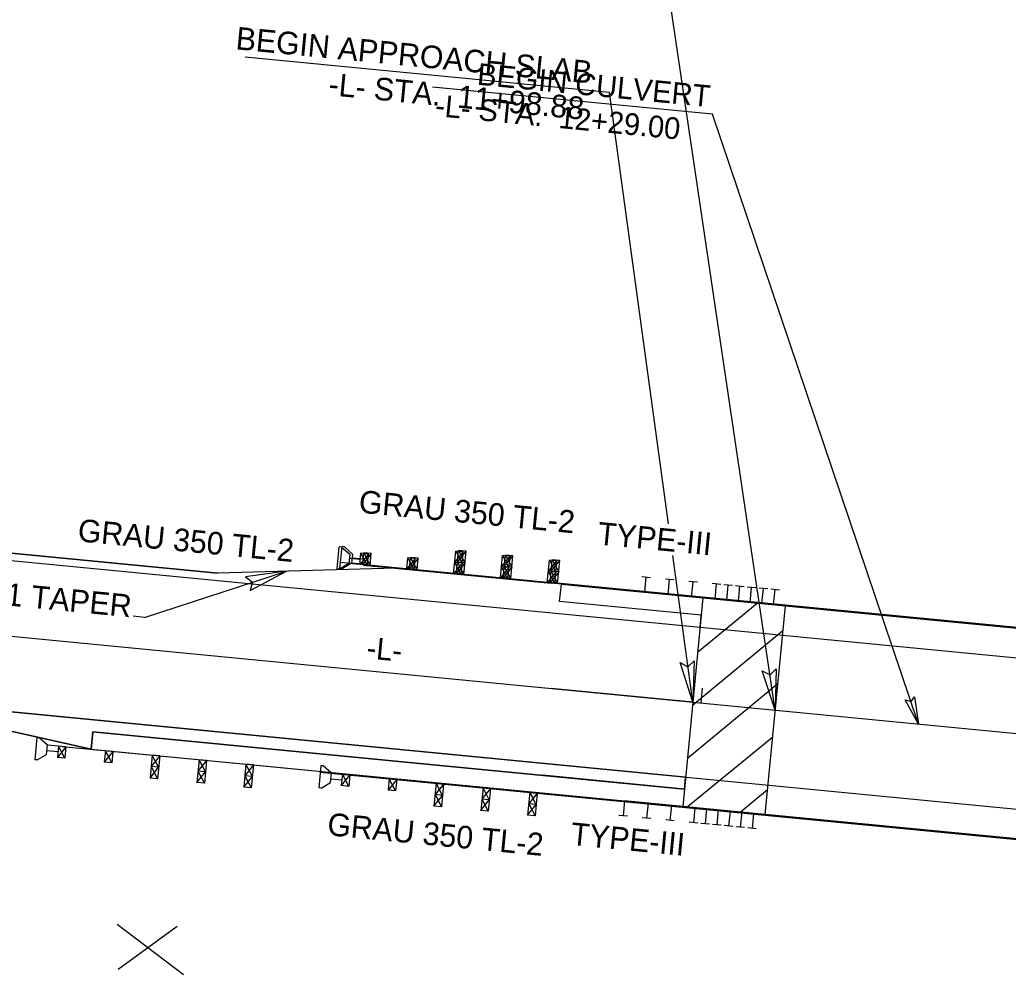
# Model space of a CAD drawing. Extents: x 2061030 to 2061632, y 912568 to 912882.
# Drawn here: x 2061138.9 to 2061270.2, y 912666.3 to 912794.9 of the extents above; entities that cross this region are included whole.
import ezdxf

# ---------------------------------------------------------------- set-up
doc = ezdxf.new("R2010")
doc.units = 0
for name, color, linetype in [('Prop Approach Slab', 7, 'Continuous'), ('Prop Approach Slab Hatching', 7, 'Continuous'), ('Prop Conc Shoulder Berm Gutter', 7, 'Continuous'), ('Prop Dimension', 7, 'Continuous'), ('Prop Dimension Text', 7, 'Continuous'), ('Prop EOT', 7, 'Continuous'), ('Prop Guardrail', 7, 'Continuous'), ('Prop Guardrail Anchor Unit CELL', 7, 'Continuous'), ('Prop Horizontal Alignment', 7, 'Continuous'), ('Prop Horizontal Alignment Station Label', 7, 'Continuous'), ('Prop Horizontal Alignment Tick Small', 7, 'Continuous'), ('Prop Paved Shoulder', 7, 'Continuous'), ('Prop Roadway Bridge', 7, 'Continuous'), ('Prop Shade Medium', 7, 'Continuous'), ('Prop Structure Anchor Unit CELL', 7, 'Continuous'), ('Prop Terminator CELL', 7, 'Continuous'), ('Scratch_Level_0', 7, 'Continuous')]:
    doc.layers.add(name, color=color, linetype=linetype)

msp = doc.modelspace()

# ---------------------------------------------------------------- linework, layer by layer
at = {"layer": 'Prop Approach Slab'}
for p, q in [((2061229.63, 912718.13), (2061226.95, 912690.43)), ((2061229.63, 912718.13), (2061240.58, 912717.07)), ((2061226.95, 912690.43), (2061237.9, 912689.37))]:
    msp.add_line(p, q, dxfattribs=at)
at = {"layer": 'Prop Approach Slab Hatching'}
for p, q in [((2061228.93, 912710.93), (2061236.83, 912717.44)), ((2061228.25, 912703.89), (2061240.26, 912713.78)), ((2061227.57, 912696.85), (2061239.58, 912706.74)), ((2061227.56, 912690.37), (2061238.9, 912699.7)), ((2061234.6, 912689.69), (2061238.22, 912692.67))]:
    msp.add_line(p, q, dxfattribs=at)
at = {"layer": 'Prop Conc Shoulder Berm Gutter'}
for p, q in [((2061210.84, 912719.95), (2061229.63, 912718.13)), ((2061228.29, 912704.28), (2061209.5, 912706.1)), ((2061148.66, 912700.34), (2061227.17, 912692.75)), ((2061148.44, 912698.02), (2061226.95, 912690.43))]:
    msp.add_line(p, q, dxfattribs=at)
at = {"layer": 'Prop Dimension'}
for q in [(2061174.36, 912721.68), (2061154.01, 912715.68)]:
    msp.add_line((2061155.5, 912715.53), q, dxfattribs=at)
at = {"layer": 'Prop Dimension Text'}
for p, q in [((2061151.88, 912674.8), (2061160.68, 912668.11)), ((2061159.84, 912674.49), (2061151.99, 912668.8))]:
    msp.add_line(p, q, dxfattribs=at)
at = {"layer": 'Prop EOT'}
for p, q in [((2061105.95, 912726.15), (2061429.44, 912694.88)), ((2061104.02, 912706.25), (2061477.28, 912670.17))]:
    msp.add_line(p, q, dxfattribs=at)
at = {"layer": 'Prop Guardrail'}
for p, q in [((2061221.91, 912718.88), (2061209.47, 912720.08)), ((2061169.47, 912695.99), (2061219.24, 912691.17))]:
    msp.add_line(p, q, dxfattribs=at)
at = {"layer": 'Prop Guardrail Anchor Unit CELL'}
for p, q in [((2061181.07, 912721.98), (2061181.35, 912724.9)), ((2061181.66, 912724.87), (2061181.35, 912724.9)), ((2061181.66, 912724.87), (2061182.75, 912723.91)), ((2061182.75, 912723.91), (2061182.63, 912722.69)), ((2061182.7, 912723.41), (2061184.16, 912723.26)), ((2061184.09, 912722.54), (2061184.24, 912724.05)), ((2061185.23, 912723.95), (2061184.09, 912722.54)), ((2061185.23, 912723.95), (2061184.24, 912724.05)), ((2061185.09, 912722.44), (2061184.24, 912724.05)), ((2061185.09, 912722.44), (2061185.23, 912723.95)), ((2061190.31, 912721.93), (2061190.46, 912723.45)), ((2061191.45, 912723.35), (2061190.31, 912721.93)), ((2061191.45, 912723.35), (2061190.46, 912723.45)), ((2061191.31, 912721.84), (2061190.46, 912723.45)), ((2061191.31, 912721.84), (2061191.45, 912723.35)), ((2061196.53, 912721.33), (2061196.82, 912724.35)), ((2061196.68, 912722.84), (2061197.82, 912724.26)), ((2061197.82, 912724.26), (2061196.82, 912724.35)), ((2061196.82, 912724.35), (2061197.67, 912722.75)), ((2061197.53, 912721.24), (2061197.82, 912724.26)), ((2061202.75, 912720.73), (2061203.05, 912723.75)), ((2061202.9, 912722.24), (2061204.04, 912723.66)), ((2061204.04, 912723.66), (2061203.05, 912723.75)), ((2061203.05, 912723.75), (2061203.89, 912722.15)), ((2061203.75, 912720.63), (2061204.04, 912723.66)), ((2061181.37, 912721.95), (2061181.07, 912721.98)), ((2061182.63, 912722.69), (2061181.37, 912721.95)), ((2061184.09, 912722.55), (2061182.63, 912722.69)), ((2061185.09, 912722.44), (2061184.09, 912722.54)), ((2061184.59, 912722.49), (2061209.47, 912720.08)), ((2061197.67, 912722.75), (2061196.53, 912721.33)), ((2061197.67, 912722.75), (2061196.68, 912722.84)), ((2061197.53, 912721.24), (2061196.68, 912722.84)), ((2061203.89, 912722.15), (2061202.75, 912720.73)), ((2061203.89, 912722.15), (2061202.9, 912722.24)), ((2061203.75, 912720.63), (2061202.9, 912722.24)), ((2061208.97, 912720.13), (2061209.27, 912723.15)), ((2061209.12, 912721.64), (2061210.26, 912723.06)), ((2061210.26, 912723.06), (2061209.27, 912723.15)), ((2061209.27, 912723.15), (2061210.12, 912721.54)), ((2061209.97, 912720.03), (2061210.26, 912723.06)), ((2061191.31, 912721.84), (2061190.31, 912721.93)), ((2061197.53, 912721.24), (2061196.53, 912721.33)), ((2061203.75, 912720.63), (2061202.75, 912720.73)), ((2061210.12, 912721.54), (2061208.97, 912720.13)), ((2061210.12, 912721.54), (2061209.12, 912721.64)), ((2061209.97, 912720.03), (2061209.12, 912721.64)), ((2061209.97, 912720.03), (2061208.97, 912720.13)), ((2061141.23, 912699.57), (2061140.95, 912696.64)), ((2061141.53, 912699.54), (2061141.23, 912699.57)), ((2061142.62, 912698.57), (2061141.53, 912699.54)), ((2061142.5, 912697.35), (2061142.62, 912698.57)), ((2061144.09, 912698.43), (2061142.62, 912698.57)), ((2061144.09, 912698.44), (2061143.94, 912696.93)), ((2061145.08, 912698.34), (2061143.94, 912696.93)), ((2061145.08, 912698.34), (2061144.09, 912698.44)), ((2061144.94, 912696.83), (2061144.09, 912698.44)), ((2061144.58, 912698.39), (2061169.47, 912695.99)), ((2061145.08, 912698.34), (2061144.94, 912696.83)), ((2061141.25, 912696.61), (2061142.5, 912697.35)), ((2061142.55, 912697.85), (2061144.02, 912697.71)), ((2061150.31, 912697.84), (2061150.16, 912696.33)), ((2061151.3, 912697.74), (2061150.16, 912696.33)), ((2061151.3, 912697.74), (2061150.31, 912697.84)), ((2061151.16, 912696.23), (2061150.31, 912697.84)), ((2061151.3, 912697.74), (2061151.16, 912696.23)), ((2061156.53, 912697.24), (2061156.24, 912694.21)), ((2061157.52, 912697.14), (2061156.38, 912695.73)), ((2061157.52, 912697.14), (2061156.53, 912697.24)), ((2061157.38, 912695.63), (2061156.53, 912697.24)), ((2061157.52, 912697.14), (2061157.23, 912694.12)), ((2061141.25, 912696.61), (2061140.95, 912696.64)), ((2061144.94, 912696.83), (2061143.94, 912696.93)), ((2061151.16, 912696.23), (2061150.16, 912696.33)), ((2061157.38, 912695.63), (2061156.38, 912695.73)), ((2061156.38, 912695.73), (2061157.23, 912694.12)), ((2061162.75, 912696.64), (2061162.46, 912693.61)), ((2061163.74, 912696.54), (2061162.6, 912695.12)), ((2061163.74, 912696.54), (2061162.75, 912696.64)), ((2061163.6, 912695.03), (2061162.75, 912696.64)), ((2061163.74, 912696.54), (2061163.45, 912693.52)), ((2061168.97, 912696.03), (2061168.68, 912693.01)), ((2061169.97, 912695.94), (2061168.82, 912694.52)), ((2061169.97, 912695.94), (2061168.97, 912696.03)), ((2061169.82, 912694.43), (2061168.97, 912696.03)), ((2061169.97, 912695.94), (2061169.67, 912692.92)), ((2061156.24, 912694.21), (2061157.38, 912695.63)), ((2061162.46, 912693.61), (2061163.6, 912695.03)), ((2061163.6, 912695.03), (2061162.6, 912695.12)), ((2061162.6, 912695.12), (2061163.45, 912693.52)), ((2061168.68, 912693.01), (2061169.82, 912694.43)), ((2061169.82, 912694.43), (2061168.82, 912694.52)), ((2061168.82, 912694.52), (2061169.67, 912692.92)), ((2061157.23, 912694.12), (2061156.24, 912694.21)), ((2061163.45, 912693.52), (2061162.46, 912693.61)), ((2061169.67, 912692.92), (2061168.68, 912693.01))]:
    msp.add_line(p, q, dxfattribs=at)
at = {"layer": 'Prop Horizontal Alignment'}
msp.add_line((2061030.33, 912723.42), (2061621.2, 912666.3), dxfattribs=at)
at = {"layer": 'Prop Horizontal Alignment Station Label'}
for p, q in [((2061239.24, 912703.22), (2061224.98, 912799.33)), ((2061217.22, 912785.22), (2061168.86, 912789.9)), ((2061225.05, 912727.96), (2061217.22, 912785.22)), ((2061228.29, 912704.28), (2061225.62, 912723.76))]:
    msp.add_line(p, q, dxfattribs=at)
at = {"layer": 'Prop Horizontal Alignment Tick Small'}
msp.add_line((2061229.4, 912704.17), (2061229.6, 912706.16), dxfattribs=at)
at = {"layer": 'Prop Paved Shoulder'}
for p, q in [((2061106.04, 912727.15), (2061165.24, 912721.43)), ((2061210.84, 912719.95), (2061210.84, 912719.95)), ((2061229.63, 912718.13), (2061240.58, 912717.07)), ((2061148.44, 912698.02), (2061125.49, 912703.17)), ((2061148.66, 912700.34), (2061148.44, 912698.02)), ((2061227.17, 912692.75), (2061148.66, 912700.34)), ((2061226.95, 912690.43), (2061237.9, 912689.37))]:
    msp.add_line(p, q, dxfattribs=at)
msp.add_lwpolyline([(2061229.4, 912715.81), (2061210.61, 912717.63), (2061210.84, 912719.95), (2061201.36, 912720.87), (2061188.85, 912722.09), (2061165.24, 912721.43)], dxfattribs=at)
at = {"layer": 'Prop Roadway Bridge'}
for p, q in [((2061237.9, 912689.37), (2061240.58, 912717.07)), ((2061240.58, 912717.07), (2061312.49, 912710.12)), ((2061309.81, 912682.42), (2061237.9, 912689.37))]:
    msp.add_line(p, q, dxfattribs=at)
at = {"layer": 'Prop Shade Medium'}
for p, q in [((2061105.95, 912726.15), (2061229.25, 912714.23)), ((2061165.24, 912721.43), (2061106.04, 912727.15)), ((2061229.25, 912714.23), (2061229.4, 912715.81)), ((2061227.33, 912694.33), (2061104.02, 912706.25)), ((2061227.17, 912692.75), (2061227.33, 912694.33))]:
    msp.add_line(p, q, dxfattribs=at)
for points in [[(2061229.4, 912715.81), (2061210.61, 912717.63), (2061210.84, 912719.95), (2061201.36, 912720.87), (2061188.85, 912722.09), (2061165.24, 912721.43)], [(2061125.49, 912703.17), (2061148.44, 912698.02), (2061148.66, 912700.34), (2061227.17, 912692.75), (2061208.38, 912694.57), (2061227.17, 912692.75)]]:
    msp.add_lwpolyline(points, dxfattribs=at)
at = {"layer": 'Prop Structure Anchor Unit CELL'}
for p, q in [((2061222.68, 912720.81), (2061221.54, 912720.92)), ((2061221.91, 912718.88), (2061222.11, 912720.87)), ((2061225.79, 912720.51), (2061224.65, 912720.62)), ((2061225.02, 912718.58), (2061225.22, 912720.57)), ((2061228.9, 912720.21), (2061227.76, 912720.32)), ((2061228.13, 912718.28), (2061228.33, 912720.27)), ((2061232.01, 912719.91), (2061230.87, 912720.02)), ((2061231.25, 912717.98), (2061231.44, 912719.97)), ((2061233.56, 912719.76), (2061232.42, 912719.87)), ((2061232.8, 912717.83), (2061232.99, 912719.82)), ((2061235.12, 912719.61), (2061233.98, 912719.72)), ((2061234.36, 912717.68), (2061234.55, 912719.67)), ((2061236.67, 912719.46), (2061235.53, 912719.57)), ((2061235.91, 912717.53), (2061236.1, 912719.52)), ((2061238.23, 912719.31), (2061237.09, 912719.42)), ((2061237.47, 912717.38), (2061237.66, 912719.37)), ((2061240.58, 912717.07), (2061221.91, 912718.88)), ((2061239.78, 912719.16), (2061238.64, 912719.27)), ((2061239.02, 912717.23), (2061239.21, 912719.22)), ((2061219.24, 912691.17), (2061219.04, 912689.18)), ((2061237.9, 912689.37), (2061219.24, 912691.17)), ((2061222.35, 912690.87), (2061222.15, 912688.88)), ((2061225.46, 912690.57), (2061225.26, 912688.58)), ((2061219.61, 912689.13), (2061218.47, 912689.24)), ((2061228.57, 912690.27), (2061228.37, 912688.28)), ((2061230.12, 912690.12), (2061229.93, 912688.13)), ((2061231.68, 912689.97), (2061231.49, 912687.98)), ((2061233.23, 912689.82), (2061233.04, 912687.83)), ((2061234.79, 912689.67), (2061234.6, 912687.68)), ((2061236.34, 912689.52), (2061236.15, 912687.53)), ((2061222.72, 912688.83), (2061221.58, 912688.94)), ((2061225.83, 912688.53), (2061224.69, 912688.64)), ((2061228.94, 912688.23), (2061227.8, 912688.34)), ((2061230.5, 912688.08), (2061229.36, 912688.19)), ((2061232.06, 912687.93), (2061230.92, 912688.04)), ((2061233.61, 912687.78), (2061232.47, 912687.89)), ((2061235.17, 912687.63), (2061234.03, 912687.74)), ((2061236.72, 912687.48), (2061235.58, 912687.59))]:
    msp.add_line(p, q, dxfattribs=at)
at = {"layer": 'Prop Terminator CELL'}
for points in [[(2061169.51, 912719.12), (2061174.36, 912721.68), (2061168.9, 912720.91), (2061169.85, 912720.21)], [(2061228.48, 912709.76), (2061228.29, 912704.28), (2061226.6, 912709.53), (2061227.65, 912708.98)], [(2061239.37, 912708.7), (2061239.24, 912703.22), (2061237.49, 912708.45), (2061238.54, 912707.91)]]:
    msp.add_lwpolyline(points, close=True, dxfattribs=at)
at = {"layer": 'Scratch_Level_0'}
for p, q in [((2061230.91, 912782.34), (2061193.74, 912785.93)), ((2061258.27, 912701.38), (2061230.91, 912782.34)), ((2061181.44, 912722.03), (2061181.73, 912724.95)), ((2061182.04, 912724.92), (2061181.73, 912724.95)), ((2061182.04, 912724.92), (2061183.12, 912723.95)), ((2061183.12, 912723.95), (2061183, 912722.74)), ((2061183.07, 912723.45), (2061184.54, 912723.31)), ((2061184.47, 912722.58), (2061184.61, 912724.09)), ((2061185.61, 912724), (2061184.47, 912722.58)), ((2061185.61, 912724), (2061184.61, 912724.09)), ((2061185.46, 912722.49), (2061184.61, 912724.09)), ((2061185.46, 912722.49), (2061185.61, 912724)), ((2061190.69, 912721.98), (2061190.83, 912723.49)), ((2061191.83, 912723.4), (2061190.69, 912721.98)), ((2061191.83, 912723.4), (2061190.83, 912723.49)), ((2061191.68, 912721.88), (2061190.83, 912723.49)), ((2061191.68, 912721.88), (2061191.83, 912723.4)), ((2061196.91, 912721.38), (2061197.2, 912724.4)), ((2061197.05, 912722.89), (2061198.2, 912724.31)), ((2061198.2, 912724.31), (2061197.2, 912724.4)), ((2061197.2, 912724.4), (2061198.05, 912722.79)), ((2061197.9, 912721.28), (2061198.2, 912724.31)), ((2061203.13, 912720.78), (2061203.42, 912723.8)), ((2061203.27, 912722.29), (2061204.42, 912723.7)), ((2061204.42, 912723.7), (2061203.42, 912723.8)), ((2061203.42, 912723.8), (2061204.27, 912722.19)), ((2061204.12, 912720.68), (2061204.42, 912723.7)), ((2061181.75, 912722), (2061181.44, 912722.03)), ((2061181.53, 912722.87), (2061373.54, 912704.31)), ((2061183, 912722.74), (2061181.75, 912722)), ((2061184.47, 912722.59), (2061183, 912722.74)), ((2061185.46, 912722.49), (2061184.47, 912722.58)), ((2061184.96, 912722.53), (2061209.85, 912720.13)), ((2061191.68, 912721.88), (2061190.69, 912721.98)), ((2061198.05, 912722.79), (2061196.91, 912721.38)), ((2061198.05, 912722.79), (2061197.05, 912722.89)), ((2061197.9, 912721.28), (2061197.05, 912722.89)), ((2061204.27, 912722.19), (2061203.13, 912720.78)), ((2061204.27, 912722.19), (2061203.27, 912722.29)), ((2061204.12, 912720.68), (2061203.27, 912722.29)), ((2061209.35, 912720.18), (2061209.64, 912723.2)), ((2061209.5, 912721.69), (2061210.64, 912723.1)), ((2061210.64, 912723.1), (2061209.64, 912723.2)), ((2061209.64, 912723.2), (2061210.49, 912721.59)), ((2061210.35, 912720.08), (2061210.64, 912723.1)), ((2061197.9, 912721.28), (2061196.91, 912721.38)), ((2061204.12, 912720.68), (2061203.13, 912720.78)), ((2061210.49, 912721.59), (2061209.35, 912720.18)), ((2061210.49, 912721.59), (2061209.5, 912721.69)), ((2061210.35, 912720.08), (2061209.5, 912721.69)), ((2061210.35, 912720.08), (2061209.35, 912720.18)), ((2061345.22, 912707.04), (2061209.85, 912720.13)), ((2061178.91, 912695.84), (2061178.63, 912692.91)), ((2061179.22, 912695.81), (2061178.91, 912695.84)), ((2061180.31, 912694.84), (2061179.22, 912695.81)), ((2061178.83, 912695), (2061430.57, 912670.66)), ((2061180.19, 912693.62), (2061180.31, 912694.84)), ((2061181.77, 912694.7), (2061180.31, 912694.84)), ((2061181.77, 912694.71), (2061181.63, 912693.2)), ((2061182.77, 912694.62), (2061181.63, 912693.2)), ((2061182.77, 912694.62), (2061181.77, 912694.71)), ((2061182.62, 912693.1), (2061181.77, 912694.71)), ((2061182.27, 912694.66), (2061207.15, 912692.26)), ((2061182.77, 912694.62), (2061182.62, 912693.1)), ((2061178.94, 912692.88), (2061180.19, 912693.62)), ((2061180.24, 912694.12), (2061181.7, 912693.99)), ((2061182.62, 912693.1), (2061181.63, 912693.2)), ((2061187.99, 912694.11), (2061187.85, 912692.6)), ((2061188.99, 912694.01), (2061187.85, 912692.6)), ((2061188.99, 912694.01), (2061187.99, 912694.11)), ((2061188.84, 912692.5), (2061187.99, 912694.11)), ((2061188.99, 912694.01), (2061188.84, 912692.5)), ((2061194.21, 912693.51), (2061193.92, 912690.49)), ((2061195.21, 912693.41), (2061194.07, 912692)), ((2061195.21, 912693.41), (2061194.21, 912693.51)), ((2061195.06, 912691.9), (2061194.21, 912693.51)), ((2061195.21, 912693.41), (2061194.92, 912690.39)), ((2061178.94, 912692.88), (2061178.63, 912692.91)), ((2061188.84, 912692.5), (2061187.85, 912692.6)), ((2061193.92, 912690.49), (2061195.06, 912691.9)), ((2061195.06, 912691.9), (2061194.07, 912692)), ((2061194.07, 912692), (2061194.92, 912690.39)), ((2061200.44, 912692.91), (2061200.14, 912689.89)), ((2061201.43, 912692.81), (2061200.29, 912691.4)), ((2061201.43, 912692.81), (2061200.44, 912692.91)), ((2061201.28, 912691.3), (2061200.44, 912692.91)), ((2061201.43, 912692.81), (2061201.14, 912689.79)), ((2061206.66, 912692.31), (2061206.36, 912689.29)), ((2061207.65, 912692.21), (2061206.51, 912690.8)), ((2061207.65, 912692.21), (2061206.66, 912692.31)), ((2061207.51, 912690.7), (2061206.66, 912692.31)), ((2061207.15, 912692.26), (2061402.24, 912673.4)), ((2061207.65, 912692.21), (2061207.36, 912689.19)), ((2061194.92, 912690.39), (2061193.92, 912690.49)), ((2061200.14, 912689.89), (2061201.28, 912691.3)), ((2061201.28, 912691.3), (2061200.29, 912691.4)), ((2061200.29, 912691.4), (2061201.14, 912689.79)), ((2061206.36, 912689.29), (2061207.51, 912690.7)), ((2061207.51, 912690.7), (2061206.51, 912690.8)), ((2061206.51, 912690.8), (2061207.36, 912689.19)), ((2061201.14, 912689.79), (2061200.14, 912689.89)), ((2061207.36, 912689.19), (2061206.36, 912689.29))]:
    msp.add_line(p, q, dxfattribs=at)
msp.add_lwpolyline([(2061257.7, 912704.99), (2061258.27, 912701.38), (2061256.5, 912704.61), (2061257.26, 912704.38)], close=True, dxfattribs=at)

# ---------------------------------------------------------------- texts
at = {"layer": 'Prop Dimension Text'}
for s, height, p in [('8:1 TAPER', 3, (2061133.67, 912717.47)), ('-L-', 2.88, (2061184.89, 912710.1))]:
    msp.add_text(s, height=height, rotation=354.4787, dxfattribs=at).set_placement(p)
at = {"layer": 'Prop Guardrail Anchor Unit CELL'}
msp.add_text('GRAU 350 TL-2', height=3, rotation=354.4787, dxfattribs=at).set_placement((2061146.55, 912725.65))
at = {"layer": 'Prop Horizontal Alignment Station Label'}
for s, p in [('BEGIN APPROACH SLAB', (2061167.53, 912790.97)), ('-L- STA.  11+98.88', (2061179.86, 912784.88))]:
    msp.add_text(s, height=3, rotation=354.4787, dxfattribs=at).set_placement(p)
at = {"layer": 'Prop Structure Anchor Unit CELL'}
for p in [(2061215.57, 912725.23), (2061211.99, 912685.34)]:
    msp.add_text('TYPE-III', height=3, rotation=354.4787, dxfattribs=at).set_placement(p)
at = {"layer": 'Scratch_Level_0'}
for s, height, p in [('BEGIN CULVERT', 2.88, (2061199.58, 912786.27)), ('-L- STA.  12+29.00', 2.88, (2061193.99, 912782.11)), ('GRAU 350 TL-2', 3, (2061183.86, 912729.46)), ('GRAU 350 TL-2', 3, (2061179.68, 912686.63))]:
    msp.add_text(s, height=height, rotation=354.4787, dxfattribs=at).set_placement(p)

doc.saveas('drawing.dxf')
